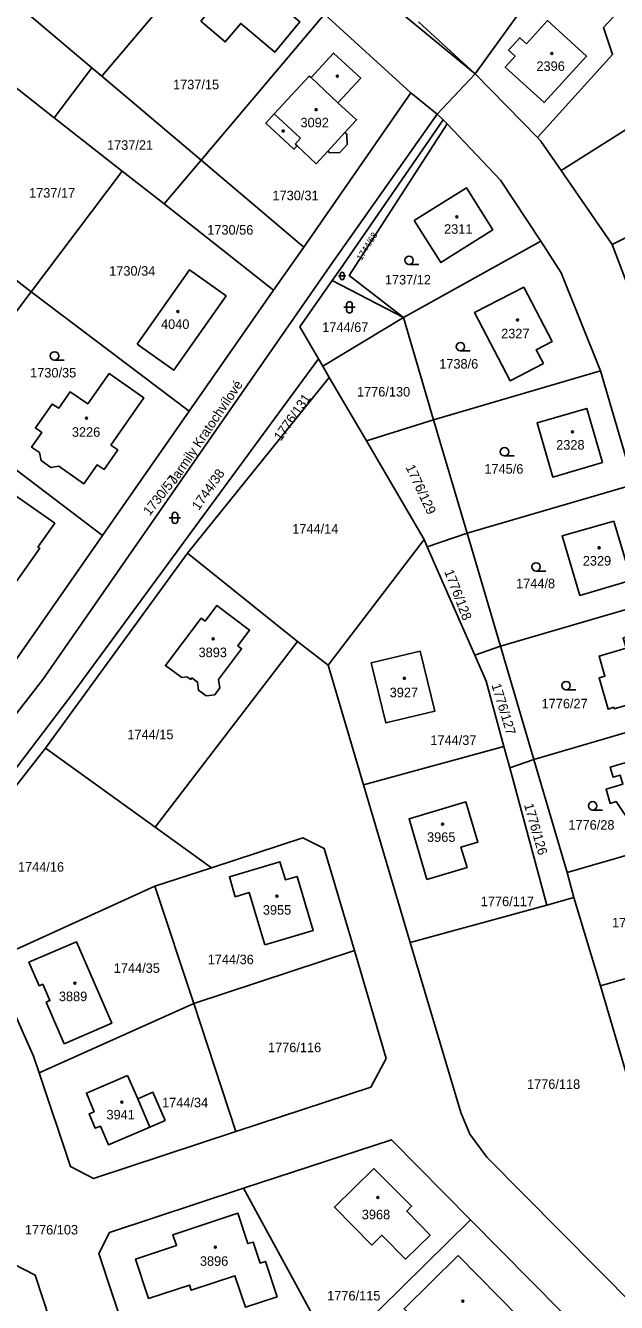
# Model space of a CAD drawing. Extents: x -679220 to -673243, y -1075091 to -1066557.
# Drawn here: x -676873.4 to -676768.1, y -1072401 to -1072173.6 of the extents above; entities that cross this region are included whole.
import ezdxf

# ---------------------------------------------------------------- set-up
doc = ezdxf.new("R2010")
doc.units = 0
for name, color, linetype in [('Hranice parcel', 7, 'Continuous'), ('Parcelní čísla', 7, 'Continuous'), ('Pop  PČ popisy', 7, 'Continuous'), ('Vnitřní kresba', 7, 'Continuous'), ('Značky budov', 7, 'Continuous'), ('Značky kultur', 7, 'Continuous')]:
    doc.layers.add(name, color=color, linetype=linetype)

msp = doc.modelspace()

# ---------------------------------------------------------------- linework, layer by layer
at = {"layer": 'Hranice parcel'}
for p, q in [((-676793.27, -1072182.15), (-676848.37, -1072136.87)), ((-676793.27, -1072182.15), (-676768.83, -1072148.2)), ((-676859.84, -1072182.62), (-676837.24, -1072155.91)), ((-676868.31, -1072190), (-676899.96, -1072165.14)), ((-676861.6, -1072181.13), (-676877.14, -1072167.98)), ((-676820.13, -1072171.54), (-676842.16, -1072197.58)), ((-676820.13, -1072171.54), (-676804.75, -1072185.58)), ((-676793.27, -1072182.15), (-676803.37, -1072172.94)), ((-676868.31, -1072190), (-676861.6, -1072181.13)), ((-676859.84, -1072182.62), (-676861.6, -1072181.13)), ((-676842.16, -1072197.58), (-676859.84, -1072182.62)), ((-676800.09, -1072189.36), (-676793.27, -1072182.15)), ((-676793.27, -1072182.15), (-676782.19, -1072193.53)), ((-676804.75, -1072185.58), (-676823.86, -1072213.06)), ((-676804.75, -1072185.58), (-676800.09, -1072189.36)), ((-676800.09, -1072189.36), (-676798.97, -1072190.38)), ((-676856.19, -1072199.51), (-676868.31, -1072190)), ((-676798.97, -1072190.38), (-676798.27, -1072191.1)), ((-676842.16, -1072197.58), (-676848.74, -1072205.36)), ((-676823.86, -1072213.06), (-676842.16, -1072197.58)), ((-676899.68, -1072199.86), (-676872.43, -1072221.01)), ((-676856.19, -1072199.51), (-676872.43, -1072221.01)), ((-676848.74, -1072205.36), (-676856.19, -1072199.51)), ((-676777.97, -1072199.39), (-676768.89, -1072212.57)), ((-676829.22, -1072220.7), (-676848.74, -1072205.36)), ((-676768.89, -1072212.57), (-676754.84, -1072205.61)), ((-676806.08, -1072225.6), (-676781.6, -1072212)), ((-676768.89, -1072212.57), (-676763.72, -1072226.16)), ((-676829.22, -1072220.7), (-676823.86, -1072213.06)), ((-676818.81, -1072218.98), (-676806.08, -1072225.6)), ((-676872.43, -1072221.01), (-676888.67, -1072242.5)), ((-676872.43, -1072221.01), (-676844.27, -1072242.28)), ((-676844.27, -1072242.28), (-676829.22, -1072220.7)), ((-676820.47, -1072234.26), (-676806.08, -1072225.6)), ((-676806.08, -1072225.6), (-676800.73, -1072243.83)), ((-676821.22, -1072232.97), (-676820.47, -1072234.26)), ((-676820.47, -1072234.26), (-676819.29, -1072236.25)), ((-676800.73, -1072243.83), (-676770.98, -1072235.1)), ((-676770.98, -1072235.1), (-676764.99, -1072255.36)), ((-676819.29, -1072236.25), (-676844.59, -1072267.57)), ((-676812.67, -1072247.56), (-676819.29, -1072236.25)), ((-676888.67, -1072242.5), (-676859.7, -1072264.4)), ((-676859.7, -1072264.4), (-676844.27, -1072242.28)), ((-676800.73, -1072243.83), (-676812.67, -1072247.56)), ((-676800.73, -1072243.83), (-676794.74, -1072264)), ((-676802.39, -1072265.11), (-676812.67, -1072247.56)), ((-676764.99, -1072255.36), (-676794.74, -1072264)), ((-676859.7, -1072264.4), (-676875.12, -1072286.5)), ((-676794.74, -1072264), (-676801.82, -1072266.42)), ((-676794.74, -1072264), (-676788.79, -1072284.16)), ((-676819.52, -1072287.53), (-676802.39, -1072265.11)), ((-676801.82, -1072266.42), (-676802.39, -1072265.11)), ((-676793.37, -1072285.72), (-676801.82, -1072266.42)), ((-676844.59, -1072267.57), (-676869.87, -1072302.33)), ((-676844.59, -1072267.57), (-676824.99, -1072283.29)), ((-676759.06, -1072275.43), (-676788.79, -1072284.16)), ((-676850.33, -1072316.37), (-676824.99, -1072283.29)), ((-676824.99, -1072283.29), (-676819.52, -1072287.53)), ((-676788.79, -1072284.16), (-676793.37, -1072285.72)), ((-676788.79, -1072284.16), (-676782.84, -1072304.32)), ((-676819.52, -1072287.53), (-676813.18, -1072308.82)), ((-676782.84, -1072304.32), (-676753.1, -1072295.59)), ((-676869.87, -1072302.33), (-676891.88, -1072330.24)), ((-676869.87, -1072302.33), (-676850.33, -1072316.37)), ((-676813.18, -1072308.82), (-676788.16, -1072302.03)), ((-676787.14, -1072305.82), (-676788.16, -1072302.03)), ((-676782.84, -1072304.32), (-676787.14, -1072305.82)), ((-676780.52, -1072330.29), (-676787.14, -1072305.82)), ((-676782.84, -1072304.32), (-676776.89, -1072324.48)), ((-676804.87, -1072336.91), (-676813.18, -1072308.82)), ((-676840.3, -1072323.62), (-676850.33, -1072316.37)), ((-676776.89, -1072324.48), (-676747.14, -1072315.75)), ((-676850.38, -1072326.91), (-676840.3, -1072323.62)), ((-676776.89, -1072324.48), (-676775.7, -1072328.93)), ((-676881.09, -1072340.82), (-676850.38, -1072326.91)), ((-676843.45, -1072347.81), (-676850.38, -1072326.91)), ((-676804.87, -1072336.91), (-676780.52, -1072330.29)), ((-676775.7, -1072328.93), (-676780.52, -1072330.29)), ((-676775.7, -1072328.93), (-676770.94, -1072344.65)), ((-676770.94, -1072344.65), (-676741.18, -1072335.91)), ((-676843.45, -1072347.81), (-676814.83, -1072338.32)), ((-676770.94, -1072344.65), (-676764.99, -1072364.81)), ((-676843.45, -1072347.81), (-676871.02, -1072360.14)), ((-676835.94, -1072370.6), (-676843.45, -1072347.81)), ((-676822.28, -1072403.26), (-676834.61, -1072380.69)), ((-676794.15, -1072386.31), (-676818.48, -1072410.3)), ((-676794.15, -1072386.31), (-676777.96, -1072402.66))]:
    msp.add_line(p, q, dxfattribs=at)
for points in [[(-676782.19, -1072193.53), (-676768.8, -1072178.75), (-676770.39, -1072173.95), (-676757.22, -1072159.8)], [(-676842.21, -1072172.77), (-676839.47, -1072169.5), (-676839.63, -1072167.61), (-676842.51, -1072165.16), (-676838.87, -1072160.82), (-676824.52, -1072172.92), (-676829.02, -1072178.3), (-676835.07, -1072173.19), (-676837.85, -1072176.48), (-676842.21, -1072172.77)], [(-676784.15, -1072176.83), (-676785.33, -1072175.75), (-676787.35, -1072177.96), (-676786.17, -1072179.04), (-676787.94, -1072180.97), (-676781.01, -1072187.31), (-676773.44, -1072179.04), (-676780.37, -1072172.7), (-676784.15, -1072176.83)], [(-676819.56, -1072195.93), (-676819.21, -1072196.26), (-676817.43, -1072196.2), (-676816.1, -1072194.76), (-676816.17, -1072192.94), (-676816.51, -1072192.63), (-676814.43, -1072190.36), (-676817.75, -1072187.33), (-676813.69, -1072182.96), (-676818.52, -1072178.49), (-676822.55, -1072182.84), (-676822.9, -1072182.6), (-676829.1, -1072189.31), (-676830.63, -1072190.95), (-676825.59, -1072195.61), (-676825.05, -1072195.02), (-676821.64, -1072198.19), (-676819.56, -1072195.93)], [(-676743.31, -1072183.24), (-676760.76, -1072188.5), (-676777.97, -1072199.39)], [(-676904.77, -1072334.29), (-676870.34, -1072290.1), (-676818.72, -1072215.8), (-676800.09, -1072189.36)], [(-676818.81, -1072218.98), (-676817.29, -1072216.91), (-676798.97, -1072190.38)], [(-676798.27, -1072191.1), (-676815.73, -1072218.12), (-676806.08, -1072225.6)], [(-676781.6, -1072212), (-676788.78, -1072201.1), (-676798.27, -1072191.1)], [(-676782.19, -1072193.53), (-676781.56, -1072194.18), (-676777.97, -1072199.39)], [(-676804.17, -1072208.31), (-676799.44, -1072215.8), (-676790.14, -1072209.96), (-676794.85, -1072202.46), (-676804.17, -1072208.31)], [(-676781.6, -1072212), (-676777.95, -1072217.6), (-676770.98, -1072235.1)], [(-676853.57, -1072230.33), (-676844.23, -1072217.11), (-676837.7, -1072221.73), (-676847.02, -1072234.95), (-676853.57, -1072230.33)], [(-676821.22, -1072232.97), (-676824.52, -1072227.27), (-676818.81, -1072218.98)], [(-676781.14, -1072233.79), (-676782.41, -1072231.34), (-676779.58, -1072229.87), (-676784.64, -1072220.15), (-676793.41, -1072224.71), (-676787.08, -1072236.85), (-676781.14, -1072233.79)], [(-676900.59, -1072339.27), (-676865.59, -1072293.33), (-676821.22, -1072232.97)], [(-676870.93, -1072249.66), (-676872.37, -1072248.67), (-676870.56, -1072246.05), (-676871.67, -1072245.26), (-676868.71, -1072241.01), (-676867.53, -1072241.76), (-676865.5, -1072238.84), (-676862.35, -1072240.99), (-676858.55, -1072235.58), (-676852.37, -1072239.9), (-676858.23, -1072248.3), (-676857, -1072249.16), (-676859.45, -1072252.68), (-676860.69, -1072251.83), (-676863.03, -1072255.19), (-676867.49, -1072252.07), (-676868.91, -1072252.31), (-676870.68, -1072251.08), (-676870.93, -1072249.66)], [(-676770.6, -1072251.43), (-676773.41, -1072241.78), (-676782.26, -1072244.36), (-676779.46, -1072254), (-676770.6, -1072251.43)], [(-676870.91, -1072266.7), (-676871.23, -1072266.48), (-676868.22, -1072262.25), (-676880.35, -1072253.8), (-676885.54, -1072261.32), (-676880.82, -1072264.69), (-676883.67, -1072268.69), (-676886.47, -1072272.81), (-676882, -1072275.9), (-676881.11, -1072274.65), (-676878.64, -1072276.36), (-676877.29, -1072274.43), (-676876.63, -1072274.89), (-676870.91, -1072266.7)], [(-676768.57, -1072261.87), (-676777.77, -1072264.48), (-676774.65, -1072275.08), (-676765.45, -1072272.35), (-676768.57, -1072261.87)], [(-676841.45, -1072279.66), (-676839.36, -1072276.9), (-676833.5, -1072281.26), (-676835.62, -1072284.05), (-676834.92, -1072284.59), (-676839.07, -1072290.06), (-676838.8, -1072291.58), (-676839.71, -1072292.81), (-676841.24, -1072292.99), (-676842.61, -1072291.99), (-676842.79, -1072290.52), (-676843.78, -1072289.77), (-676843.99, -1072290.06), (-676844.66, -1072289.58), (-676845.57, -1072289.74), (-676848.51, -1072287.58), (-676842.13, -1072279.15), (-676841.45, -1072279.66)], [(-676761.32, -1072283.04), (-676761.82, -1072283.18), (-676762.35, -1072281.34), (-676766.89, -1072282.65), (-676766.36, -1072284.5), (-676771.2, -1072285.89), (-676770.16, -1072289.49), (-676771.21, -1072289.79), (-676769.61, -1072295.33), (-676768.56, -1072295.02), (-676768.49, -1072295.27), (-676758.51, -1072292.39), (-676761.32, -1072283.04)], [(-676803.09, -1072285), (-676800.48, -1072295.69), (-676809.21, -1072297.82), (-676811.83, -1072287.11), (-676803.09, -1072285)], [(-676788.16, -1072302.03), (-676791.33, -1072290.37), (-676793.37, -1072285.72)], [(-676752.72, -1072312.34), (-676755.84, -1072301.75), (-676769.22, -1072305.69), (-676768.69, -1072307.48), (-676767.44, -1072307.11), (-676766.96, -1072308.74), (-676769.95, -1072309.62), (-676769.21, -1072312.14), (-676768.15, -1072311.83), (-676765.24, -1072316.13), (-676752.72, -1072312.34)], [(-676801.88, -1072325.68), (-676805.08, -1072314.87), (-676794.96, -1072311.89), (-676792.8, -1072319.05), (-676795.82, -1072319.94), (-676794.74, -1072323.55), (-676801.88, -1072325.68)], [(-676814.83, -1072338.32), (-676820.2, -1072320.18), (-676824.04, -1072318.28), (-676840.3, -1072323.62)], [(-676830.81, -1072337.34), (-676833.55, -1072328.03), (-676836.05, -1072328.76), (-676837.1, -1072325.22), (-676828.1, -1072322.54), (-676827.13, -1072325.73), (-676825.02, -1072325.15), (-676822.17, -1072334.81), (-676830.81, -1072337.34)], [(-676866.54, -1072354.96), (-676869.74, -1072347.57), (-676869.09, -1072347.28), (-676870.37, -1072344.36), (-676871.02, -1072344.64), (-676872.83, -1072340.44), (-676864.36, -1072336.78), (-676858.08, -1072351.31), (-676866.54, -1072354.96)], [(-676738.25, -1072428.57), (-676791.19, -1072375.15), (-676794.22, -1072371.04), (-676795.86, -1072367.2), (-676804.87, -1072336.91)], [(-676814.83, -1072338.32), (-676809.15, -1072357.61), (-676811.87, -1072362.71), (-676835.94, -1072370.6)], [(-676881.09, -1072340.82), (-676875.87, -1072348.42), (-676872.01, -1072357.2), (-676871.02, -1072360.14)], [(-676871.02, -1072360.14), (-676865.41, -1072376.83), (-676861.32, -1072378.99), (-676835.94, -1072370.6)], [(-676855.24, -1072360.61), (-676853.45, -1072364.76), (-676850.73, -1072363.61), (-676848.58, -1072368.63), (-676851.3, -1072369.8), (-676858.66, -1072372.95), (-676860.08, -1072369.63), (-676861, -1072370.02), (-676862.1, -1072367.44), (-676861.21, -1072367.06), (-676862.6, -1072363.76), (-676855.24, -1072360.61)], [(-676834.61, -1072380.69), (-676808.21, -1072372.05), (-676794.15, -1072386.31)], [(-676811.36, -1072377.16), (-676804.63, -1072383.92), (-676805.48, -1072384.78), (-676801.34, -1072389.04), (-676805.73, -1072393.33), (-676809.92, -1072389.06), (-676811.71, -1072390.82), (-676818.38, -1072384.06), (-676811.36, -1072377.16)], [(-676853.39, -1072413.53), (-676860.35, -1072392.34), (-676858.48, -1072388.58), (-676834.61, -1072380.69)], [(-676828.6, -1072400.03), (-676834.26, -1072401.9), (-676836.11, -1072396.3), (-676843.91, -1072398.87), (-676844.23, -1072397.94), (-676851.52, -1072400.33), (-676853.83, -1072393.32), (-676846.53, -1072390.9), (-676847.16, -1072388.99), (-676835.6, -1072385.16), (-676833.81, -1072390.57), (-676832.86, -1072390.28), (-676831.6, -1072394.03), (-676830.65, -1072393.74), (-676828.6, -1072400.03)], [(-676865.11, -1072416.25), (-676871.72, -1072396.17), (-676875.51, -1072394.24), (-676901.03, -1072403.13)], [(-676796.35, -1072392.68), (-676785.57, -1072403.58), (-676792.16, -1072410.12), (-676796.46, -1072405.79), (-676799.47, -1072408.71), (-676805.95, -1072402.17), (-676796.35, -1072392.68)]]:
    msp.add_lwpolyline(points, dxfattribs=at)
at = {"layer": 'Vnitřní kresba'}
for p, q in [((-676817.75, -1072187.33), (-676822.55, -1072182.84)), ((-676829.1, -1072189.31), (-676824.4, -1072193.65)), ((-676824.4, -1072193.65), (-676825.38, -1072194.72)), ((-676819.56, -1072195.93), (-676816.51, -1072192.63)), ((-676825.38, -1072194.72), (-676825.05, -1072195.02)), ((-676851.3, -1072369.8), (-676853.45, -1072364.76))]:
    msp.add_line(p, q, dxfattribs=at)
at = {"layer": 'Značky budov'}
for centre in [(-676779.65, -1072178.54), (-676817.86, -1072182.57), (-676821.65, -1072188.56), (-676827.5, -1072192.36), (-676796.55, -1072207.64), (-676846.27, -1072224.5), (-676785.73, -1072226.03), (-676862.56, -1072243.5), (-676775.95, -1072245.96), (-676771.21, -1072266.59), (-676840, -1072282.82), (-676805.92, -1072289.86), (-676799.09, -1072315.85), (-676828.62, -1072328.66), (-676864.63, -1072344.16), (-676856.26, -1072365.36), (-676810.64, -1072382.34), (-676839.61, -1072391.22), (-676795.48, -1072400.82)]:
    msp.add_circle(centre, 0.175, dxfattribs=at)
at = {"layer": 'Značky kultur'}
for p, q in [((-676805.08, -1072216.15), (-676803.33, -1072216.15)), ((-676817.66, -1072218.19), (-676816.32, -1072218.19)), ((-676817.33, -1072217.85), (-676817.33, -1072218.53)), ((-676816.66, -1072218.53), (-676816.66, -1072217.85)), ((-676816.7, -1072223.77), (-676814.7, -1072223.77)), ((-676816.2, -1072223.27), (-676816.2, -1072224.27)), ((-676815.2, -1072224.27), (-676815.2, -1072223.27)), ((-676795.93, -1072231.53), (-676794.18, -1072231.53)), ((-676868.28, -1072233.18), (-676866.53, -1072233.18)), ((-676788.07, -1072250.24), (-676786.32, -1072250.24)), ((-676847.81, -1072261.29), (-676845.81, -1072261.29)), ((-676847.31, -1072260.79), (-676847.31, -1072261.79)), ((-676846.31, -1072261.79), (-676846.31, -1072260.79)), ((-676782.44, -1072270.76), (-676780.69, -1072270.76)), ((-676777.08, -1072291.9), (-676775.33, -1072291.9)), ((-676772.35, -1072313.33), (-676770.6, -1072313.33))]:
    msp.add_line(p, q, dxfattribs=at)
for centre in [(-676805.08, -1072215.4), (-676795.93, -1072230.78), (-676868.28, -1072232.43), (-676788.07, -1072249.49), (-676782.44, -1072270.01), (-676777.08, -1072291.15), (-676772.35, -1072312.58)]:
    msp.add_circle(centre, 0.75, dxfattribs=at)
for centre, radius, start, end in [((-676816.99, -1072217.86), 0.335, 0, 180), ((-676816.99, -1072218.53), 0.335, 180, 359.9879), ((-676815.7, -1072223.27), 0.5, 0, 180), ((-676815.7, -1072224.27), 0.5, 180, 359.9879), ((-676846.81, -1072260.79), 0.5, 0, 180), ((-676846.81, -1072261.79), 0.5, 180, 359.9879)]:
    msp.add_arc(centre, radius, start, end, dxfattribs=at)

# ---------------------------------------------------------------- texts
at = {"layer": 'Parcelní čísla'}
for s, p in [('2396', (-676782.37, -1072181.65)), ('1737/15', (-676847.15, -1072184.93)), ('3092', (-676824.43, -1072191.71)), ('1737/21', (-676858.92, -1072195.71)), ('1737/17', (-676872.81, -1072204.23)), ('1730/31', (-676829.42, -1072204.69)), ('1730/56', (-676841.05, -1072210.82)), ('2311', (-676798.83, -1072210.67)), ('1730/34', (-676858.53, -1072218.14)), ('1737/12', (-676809.39, -1072219.7)), ('4040', (-676849.29, -1072227.62)), ('1744/67', (-676820.55, -1072228.16)), ('2327', (-676788.66, -1072229.29)), ('1738/6', (-676799.7, -1072234.69)), ('1730/35', (-676872.62, -1072236.27)), ('1776/130', (-676814.36, -1072239.66)), ('3226', (-676865.18, -1072246.83)), ('2328', (-676778.85, -1072249.12)), ('1745/6', (-676791.65, -1072253.4)), ('1744/14', (-676825.9, -1072264.08)), ('2329', (-676774.11, -1072269.77)), ('1744/8', (-676786, -1072273.82)), ('3893', (-676842.6, -1072286.09)), ('3927', (-676808.53, -1072293.23)), ('1776/27', (-676781.45, -1072295.21)), ('1744/15', (-676855.29, -1072300.72)), ('1744/37', (-676801.28, -1072301.73)), ('1776/28', (-676776.68, -1072316.82)), ('3965', (-676801.87, -1072318.99)), ('1744/16', (-676874.79, -1072324.3)), ('3955', (-676831.14, -1072331.97)), ('1776/117', (-676792.29, -1072330.45)), ('1776/29', (-676768.89, -1072334.23)), ('1744/36', (-676840.97, -1072340.79)), ('1744/35', (-676857.71, -1072342.33)), ('3889', (-676867.5, -1072347.37)), ('1776/116', (-676830.22, -1072356.46)), ('1776/118', (-676784.05, -1072363)), ('1744/34', (-676849.11, -1072366.29)), ('3941', (-676859.01, -1072368.44)), ('3968', (-676813.5, -1072386.23)), ('1776/103', (-676873.56, -1072388.94)), ('3896', (-676842.36, -1072394.52)), ('1776/115', (-676819.67, -1072400.69))]:
    msp.add_text(s, height=1.7, dxfattribs=at).set_placement(p)
for s, height, rotation, p in [('1744/68', 1.14, 58, (-676813.56, -1072215.54)), ('1776/131', 1.7, 55, (-676827.94, -1072247.71)), ('1744/38', 1.7, 55, (-676842.56, -1072260.06)), ('1776/129', 1.7, 295, (-676805.73, -1072252.26)), ('1730/57', 1.7, 52, (-676851.31, -1072261.02)), ('1776/128', 1.7, 291, (-676798.82, -1072270.85)), ('1776/127', 1.7, 287, (-676790.4, -1072291.05)), ('1776/126', 1.7, 286, (-676784.6, -1072312.39))]:
    msp.add_text(s, height=height, rotation=rotation, dxfattribs=at).set_placement(p)
at = {"layer": 'Pop  PČ popisy'}
msp.add_text('Jarmily Kratochvílové', height=1.7, rotation=56, dxfattribs=at).set_placement((-676846.73, -1072255.41))

doc.saveas('drawing.dxf')
